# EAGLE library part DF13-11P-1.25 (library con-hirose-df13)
DF13-11P 1.25mm Pitch Miniature Crimping Connector.
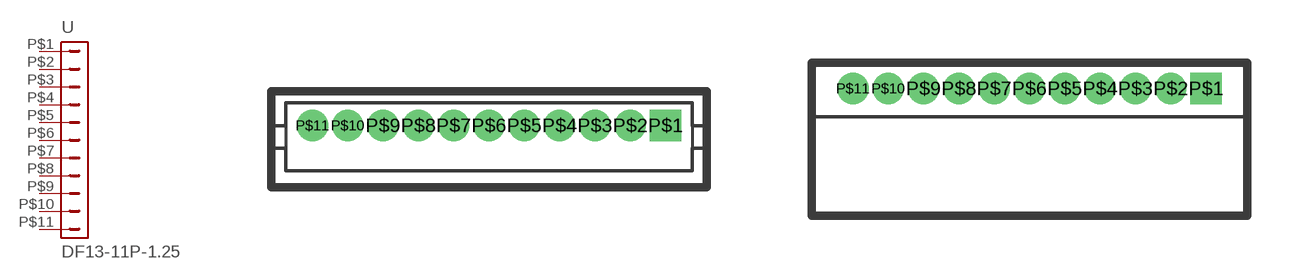
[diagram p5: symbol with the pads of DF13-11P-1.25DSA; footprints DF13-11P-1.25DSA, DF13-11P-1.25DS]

Designator prefix -

## DF13-11P-1.25DSA  [DF13-11P-1.25DSA]
P$1  1  pas
P$2  2  pas
P$3  3  pas
P$4  4  pas
P$5  5  pas
P$6  6  pas
P$7  7  pas
P$8  8  pas
P$9  9  pas
P$10  10  pas
P$11  11  pas

## DF13-11P-1.25DS  [DF13-11P-1.25DS]
Pads as for DF13-11P-1.25DSA

## DF13-11P-1.25V  [DF13C-11P-1.25V]
Pads as for DF13-11P-1.25DSA

## DF13-11P-1.25H  [DF13A-11P-1.25H]
Pads as for DF13-11P-1.25DSA

## Footprint DF13-11P-1.25DSA (pad centres in mm)
Single Row Straight Pin Header (Through hole)
drill 0.6 pad 1.016 square: P$1 6.25,0
drill 0.6 pad 1.016 round: P$2 5,0; P$3 3.75,0; P$4 2.5,0; P$5 1.25,0; P$6 0,0; P$7 -1.25,0; P$8 -2.5,0; P$9 -3.75,0; P$10 -5,0; P$11 -6.25,0

## Footprint DF13-11P-1.25DS (pad centres in mm)
Single Row Right Angle Pin Header (Through hole)
drill 0.6 pad 1.016 square: P$1 6.25,0
drill 0.6 pad 1.016 round: P$2 5,0; P$3 3.75,0; P$4 2.5,0; P$5 1.25,0; P$6 0,0; P$7 -1.25,0; P$8 -2.5,0; P$9 -3.75,0; P$10 -5,0; P$11 -6.25,0

## Footprint DF13C-11P-1.25V (pad centres in mm)
Single Row Straight Pin Header (SMT)
smd 1.6 x 2.2: M$0 8.7,-1.8; M$1 -8.7,-1.8
smd 0.7 x 1.8: P$1 -6.25,0.9; P$2 -5,0.9; P$3 -3.75,0.9; P$4 -2.5,0.9; P$5 -1.25,0.9; P$6 0,0.9; P$7 1.25,0.9; P$8 2.5,0.9; P$9 3.75,0.9; P$10 5,0.9; P$11 6.25,0.9

## Footprint DF13A-11P-1.25H (pad centres in mm)
Single Row Straight Pin Header (SMT)
smd 1.6 x 2.2: M$0 -8.6,2.4; M$1 8.6,2.4
smd 0.7 x 1.8: P$1 -6.25,-0.9; P$2 -5,-0.9; P$3 -3.75,-0.9; P$4 -2.5,-0.9; P$5 -1.25,-0.9; P$6 0,-0.9; P$7 1.25,-0.9; P$8 2.5,-0.9; P$9 3.75,-0.9; P$10 5,-0.9; P$11 6.25,-0.9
